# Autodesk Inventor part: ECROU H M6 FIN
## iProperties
Created: 2004-11
Part Number: ECROU H M6 FIN
Document SubType Name: Modeling
Designer: Bruno
Manufacturer: Standard
Standards Organization: Custom
Author: Bruno
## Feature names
1. Base1
